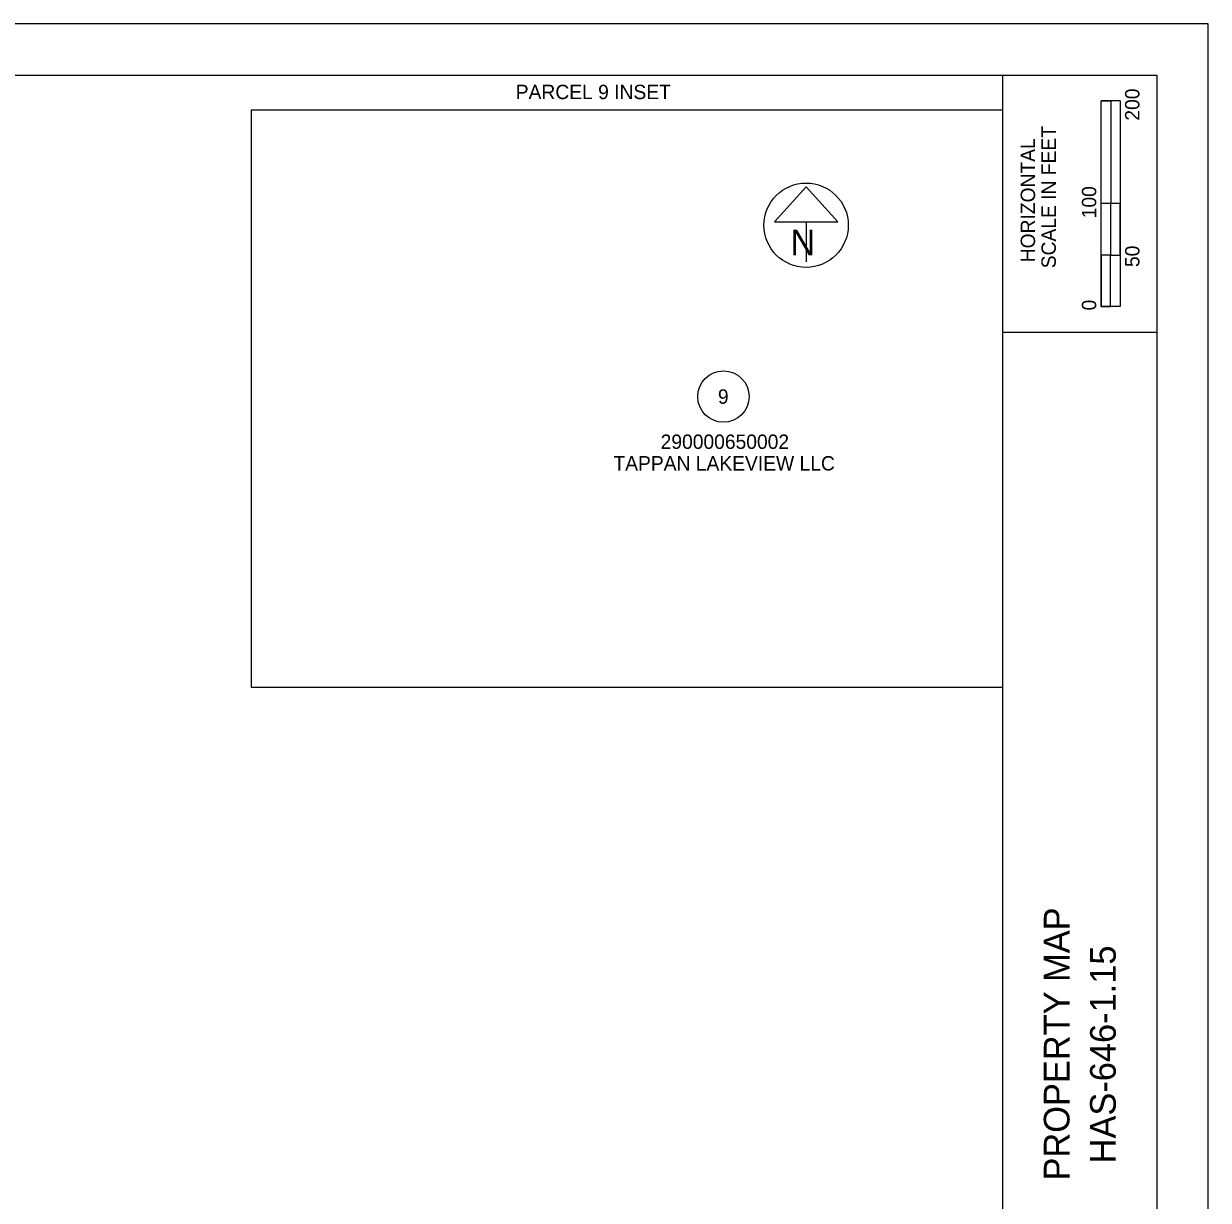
# Model space of a CAD drawing. Extents: x -28471 to 52, y -842 to 30.
# Drawn here: x 22.48 to 34, y 10.56 to 22 of the extents above; entities that cross this region are included whole.
import ezdxf

# ---------------------------------------------------------------- set-up
doc = ezdxf.new("R2010")
doc.units = 0
for name, color, linetype in [('_CIVIL_CONSTRUCTION', 7, 'Continuous'), ('Default', 7, 'Continuous'), ('RW_X_CL', 7, 'Continuous'), ('RW_X_CL_100_Bearings', 7, 'Continuous'), ('RW_X_CL_100_Cardinal_Points', 7, 'Continuous'), ('RW_X_CL_100_Curve_Data', 7, 'Continuous')]:
    doc.layers.add(name, color=color, linetype=linetype)

msp = doc.modelspace()

# ---------------------------------------------------------------- linework, layer by layer
at = {"layer": '_CIVIL_CONSTRUCTION'}
msp.add_lwpolyline([(0, 0), (34, 0), (34, 22), (0, 22)], close=True, dxfattribs=at)
at = {"layer": 'RW_X_CL'}
for p, q in [((32, 0.5), (32, 21.5)), ((32, 19), (33.5, 19))]:
    msp.add_line(p, q, dxfattribs=at)
msp.add_lwpolyline([(1.5, 21.5), (33.5, 21.5), (33.5, 0.5), (1.5, 0.5)], close=True, dxfattribs=at)
at = {"layer": 'RW_X_CL_100_Bearings'}
for p, q in [((32.957, 19.25), (32.957, 21.25)), ((33.144, 21.25), (32.957, 21.25)), ((32.957, 20.25), (32.957, 21.25)), ((32.957, 21.25), (33.05, 21.25)), ((33.05, 21.25), (33.051, 21.25)), ((33.051, 21.25), (33.051, 20.25)), ((33.144, 21.25), (33.144, 19.25)), ((33.051, 20.25), (32.957, 20.25)), ((33.143, 20.25), (33.05, 20.25)), ((33.05, 20.25), (33.05, 19.75)), ((33.143, 19.75), (33.143, 20.25)), ((33.05, 19.75), (32.957, 19.75)), ((32.957, 19.75), (32.957, 19.25)), ((33.05, 19.25), (33.05, 19.75)), ((33.05, 19.75), (33.143, 19.75)), ((33.144, 19.25), (32.957, 19.25)), ((32.957, 19.25), (33.05, 19.25))]:
    msp.add_line(p, q, dxfattribs=at)
at = {"layer": 'RW_X_CL_100_Cardinal_Points'}
msp.add_circle((30.088, 20.04), 0.41, dxfattribs=at)
at = {"layer": 'RW_X_CL_100_Curve_Data'}
for p, q in [((30.088, 20.413), (29.78, 20.072)), ((30.395, 20.072), (30.088, 20.413)), ((29.78, 20.072), (30.395, 20.072)), ((30.088, 20.072), (30.088, 19.685))]:
    msp.add_line(p, q, dxfattribs=at)
msp.add_lwpolyline([(24.69, 15.548), (32, 15.548), (32, 21.16), (24.69, 21.16)], close=True, dxfattribs=at)
for centre, radius in [((30.088, 20.04), 0.41), ((29.284, 18.373), 0.25)]:
    msp.add_circle(centre, radius, dxfattribs=at)

# ---------------------------------------------------------------- texts
at = {"layer": 'Default'}
for s, p in [('290000650002', (28.673, 17.864)), ('TAPPAN LAKEVIEW LLC', (28.214, 17.654))]:
    msp.add_text(s, height=0.14, rotation=360, dxfattribs=at).set_placement(p)
at = {"layer": 'RW_X_CL_100_Bearings'}
for s, height, p in [('200', 0.14, (33.33, 21.057)), ('SCALE IN FEET', 0.14, (32.517, 19.621)), ('HORIZONTAL', 0.14, (32.315, 19.679)), ('100', 0.14, (32.91, 20.107)), ('50', 0.14, (33.33, 19.633)), ('0', 0.14, (32.91, 19.211)), ('PROPERTY MAP', 0.25, (32.65, 10.748)), ('HAS-646-1.15', 0.25, (33.1, 10.915))]:
    msp.add_text(s, height=height, rotation=90, dxfattribs=at).set_placement(p)
at = {"layer": 'RW_X_CL_100_Curve_Data'}
for s, height, p in [('PARCEL 9 INSET', 0.14, (27.264, 21.266)), ('N', 0.25, (29.936, 19.748))]:
    msp.add_text(s, height=height, dxfattribs=at).set_placement(p)
msp.add_text('9', height=0.14, rotation=360, dxfattribs=at).set_placement((29.23, 18.303))

doc.saveas('drawing.dxf')
